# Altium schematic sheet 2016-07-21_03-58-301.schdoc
size 433 x 127 mm; SheetNumber: 1; SheetTotal: 1
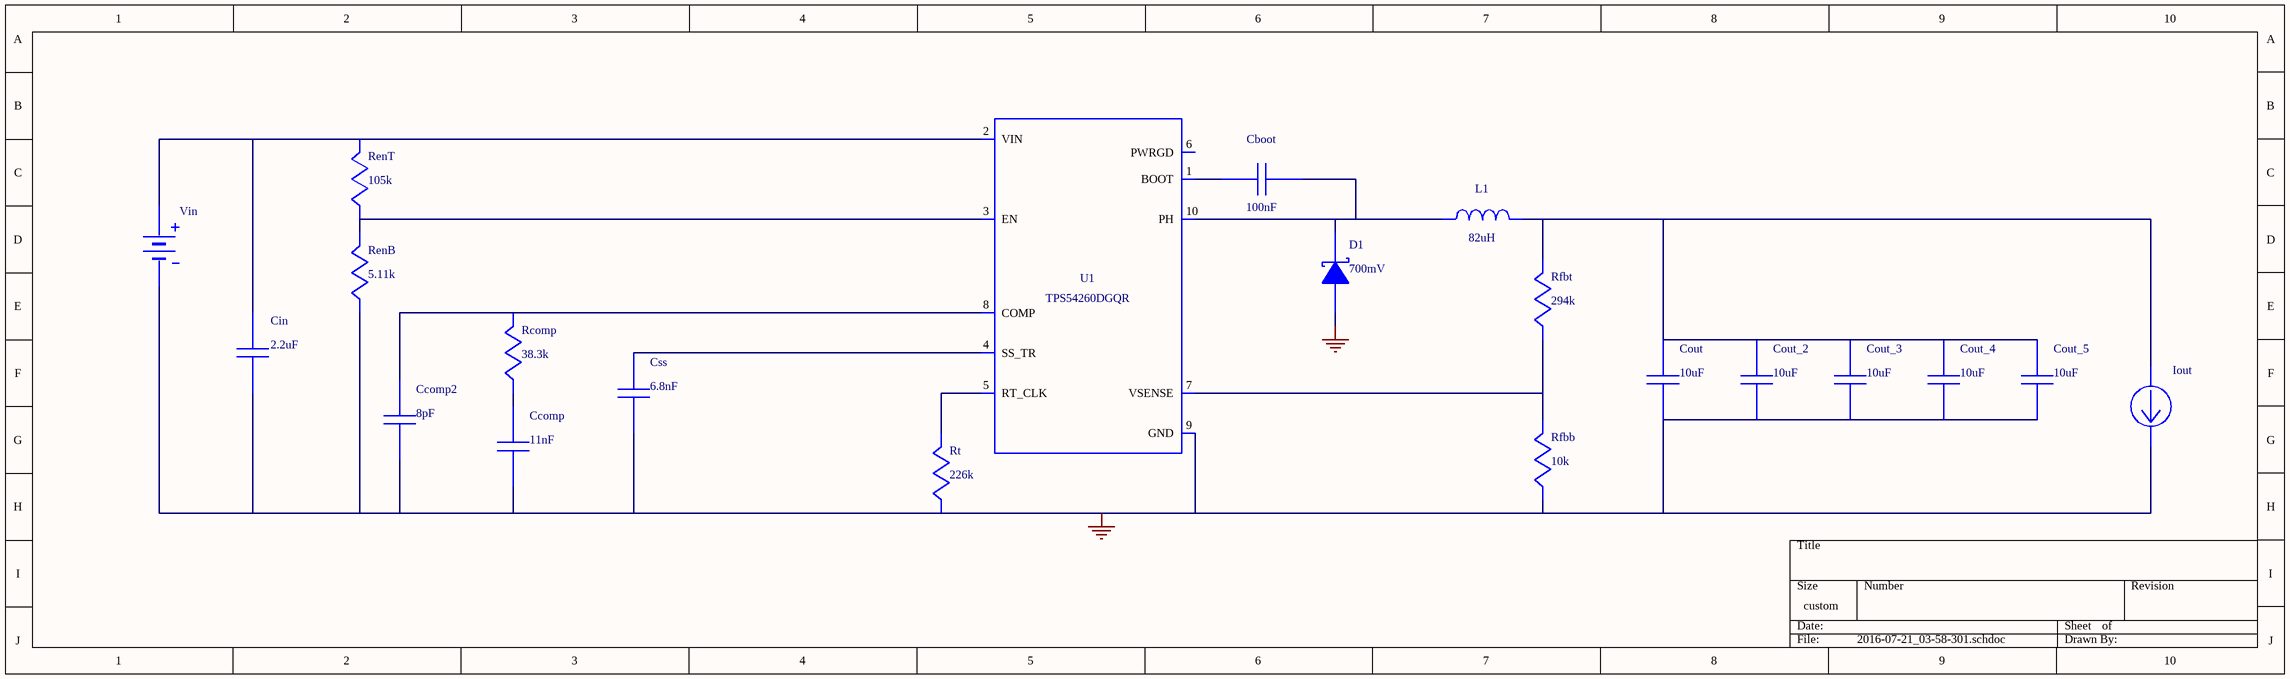
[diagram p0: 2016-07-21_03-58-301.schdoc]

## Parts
Cboot  value 100nF  (hidden comment: GRM155R61A104KA01D)
Ccomp  value 11nF  (hidden comment: GRM3195C1H113JA01D)
Ccomp2  value 8pF  (hidden comment: GQM2195C2A8R0CB01D)
Cin  value 2.2uF  (hidden comment: C3225X7R2A225K230AB)
Cout  value 10uF  (hidden comment: GRM32ER7YA106KA12L)
Cout_2  value 10uF  (hidden comment: GRM32ER7YA106KA12L)
Cout_3  value 10uF  (hidden comment: GRM32ER7YA106KA12L)
Cout_4  value 10uF  (hidden comment: GRM32ER7YA106KA12L)
Cout_5  value 10uF  (hidden comment: GRM32ER7YA106KA12L)
Css  value 6.8nF  (hidden comment: CC0805KRX7R9BB682)
D1  value 700mV  (hidden comment: B260A-13-F)
Iout  WB_CURRENT_LOAD  (value not drawn)
L1  value 82uH  (hidden comment: PM2110-820K-RC)
Rcomp  value 38.3k  (hidden comment: CRCW040238K3FKED)
RenB  value 5.11k  (hidden comment: CRCW04025K11FKED)
RenT  value 105k  (hidden comment: CRCW0402105KFKED)
Rfbb  value 10k  (hidden comment: CRCW040210K0FKED)
Rfbt  value 294k  (hidden comment: CRCW0402294KFKED)
Rt  value 226k  (hidden comment: CRCW0402226KFKED)
U1  TPS54140DGQR  (value not drawn)
Vin  WB_BATTERY  (value not drawn)

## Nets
0: Ccomp.2 Ccomp2.2 Cin.2 Cout.2 Cout_2.2 Cout_3.2 Cout_4.2 Cout_5.2 Css.2 D1.2(A) Iout.2(-) RenB.2 Rfbb.2 Rt.2 U1.9(GND) U1.11(EPAD) Vin.2(-)
NetCboot_1: Cboot.1 U1.1(BOOT)
NetCboot_2: Cboot.2 D1.1(K) L1.2 U1.10(PH)
NetCcomp2_1: Ccomp2.1 Rcomp.1 U1.8(COMP)
NetCcomp_1: Ccomp.1 Rcomp.2
NetCin_1: Cin.1 RenT.1 U1.2(VIN) Vin.1(+)
NetCout_1: Cout.1 Cout_2.1 Cout_3.1 Cout_4.1 Cout_5.1 Iout.1(+) L1.1 Rfbt.1
NetCss_1: Css.1 U1.4(SS_TR)
NetRenB_1: RenB.1 RenT.2 U1.3(EN)
NetRfbb_1: Rfbb.1 Rfbt.2 U1.7(VSENSE)
NetRt_1: Rt.1 U1.5(RT_CLK)

Not connected (* = marked no-connect by the designer): U1 6(PWRGD)

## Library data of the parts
Cboot = GRM155R61A104KA01D: GRM155R61A104KA0; Manufacturer Name: MuRata
Ccomp = GRM3195C1H113JA01D: GRM3195C1H113JA0; Manufacturer Name: MuRata
Ccomp2 = GQM2195C2A8R0CB01D: GQM2195C2A8R0CB0; Manufacturer Name: MuRata
Cin = C3225X7R2A225K230AB: C3225X7R2A225K23; Manufacturer Name: TDK
Cout Cout_2-Cout_5 = GRM32ER7YA106KA12L: GRM32ER7YA106KA1; Manufacturer Name: MuRata
Css = CC0805KRX7R9BB682: CC0805KRX7R9BB68; Manufacturer Name: Yageo America
D1 = B260A-13-F: Manufacturer Name: Diodes Inc.
L1 = PM2110-820K-RC: Manufacturer Name: Bourns
Rcomp = CRCW040238K3FKED: Manufacturer Name: Vishay-Dale
RenB = CRCW04025K11FKED: Manufacturer Name: Vishay-Dale
RenT = CRCW0402105KFKED: Manufacturer Name: Vishay-Dale
Rfbb = CRCW040210K0FKED: Manufacturer Name: Vishay-Dale
Rfbt = CRCW0402294KFKED: Manufacturer Name: Vishay-Dale
Rt = CRCW0402226KFKED: Manufacturer Name: Vishay-Dale
U1 = TPS54140DGQR: TPS54260DGQR; Manufacturer Name: Texas Instruments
